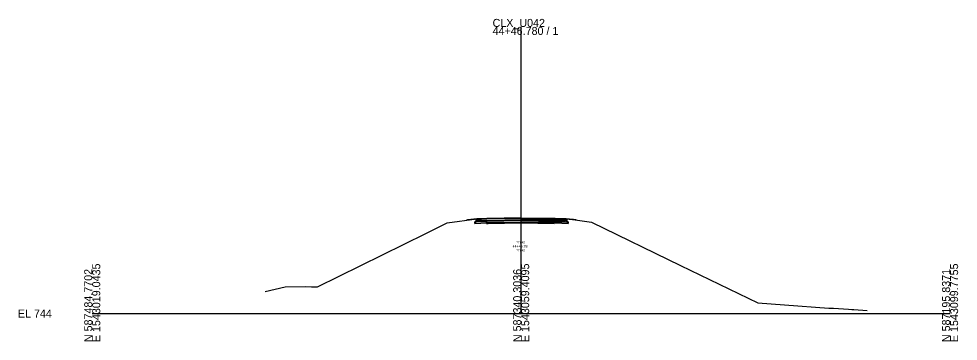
# Model space of a CAD drawing. Extents: x -26 to 1603, y -10 to 5557.
# Drawn here: x 1274.3 to 1602.8, y -9.7 to 103.1 of the extents above; entities that cross this region are included whole.
import ezdxf

# ---------------------------------------------------------------- set-up
doc = ezdxf.new("R2010")
doc.units = 0
for name, color, linetype in [('GK_Cells', 7, 'Continuous'), ('XS_P_Annotation', 7, 'Continuous'), ('XS_P_Earthwork_Shapes', 7, 'Continuous'), ('XS_P_Finished_Grade', 7, 'Continuous'), ('XS_P_Pavt_Layers', 7, 'Continuous'), ('XS_P_Pavt_Surface', 7, 'Continuous'), ('XS_P_Shoulder_Layers', 7, 'Continuous'), ('XS_P_Shoulder_Surface', 7, 'Continuous'), ('XS_P_Subgrade', 7, 'Continuous'), ('XS_X_Ground_Line', 7, 'Continuous'), ('XS_X_Pavt', 7, 'Continuous')]:
    doc.layers.add(name, color=color, linetype=linetype)

msp = doc.modelspace()

# ---------------------------------------------------------------- linework, layer by layer
at = {"layer": 'GK_Cells'}
for p, q in [((1450, 0), (1450, 100.27)), ((1300, 0), (1450, 0)), ((1450, 0), (1600, 0))]:
    msp.add_line(p, q, dxfattribs=at)
at = {"layer": 'XS_P_Earthwork_Shapes'}
for points in [[(1430.85, 32.64), (1433.47, 33), (1431.19, 32.81)], [(1430.85, 32.64), (1433.47, 33), (1431.19, 32.81)], [(1433.47, 33), (1431.19, 32.81), (1430.85, 32.64)], [(1433.47, 33), (1431.19, 32.81), (1430.85, 32.64)], [(1434.54, 33.09), (1433.47, 33), (1434.49, 33.14), (1434.54, 33.14)], [(1434.54, 33.09), (1433.47, 33), (1434.49, 33.14), (1434.54, 33.14)], [(1434.54, 33.09), (1433.47, 33), (1434.49, 33.14), (1434.54, 33.14)], [(1434.54, 33.09), (1433.47, 33), (1434.49, 33.14), (1434.54, 33.14)], [(1434.54, 33.14), (1438.46, 33.23), (1449.95, 33.42), (1461.72, 33.3), (1462.03, 33.29), (1465.5, 33.23), (1465.5, 32.48), (1462.03, 32.54), (1461.72, 32.55), (1461.49, 32.55), (1449.95, 32.67), (1438.46, 32.48), (1437.93, 32.47), (1434.54, 32.39), (1434.54, 32.82), (1434.61, 32.83), (1434.61, 33.1), (1434.54, 33.09)], [(1434.54, 33.14), (1438.46, 33.23), (1449.95, 33.42), (1461.72, 33.3), (1462.03, 33.29), (1465.5, 33.23), (1465.5, 32.48), (1462.03, 32.54), (1461.72, 32.55), (1461.49, 32.55), (1449.95, 32.67), (1438.46, 32.48), (1437.93, 32.47), (1434.54, 32.39), (1434.54, 32.82), (1434.61, 32.83), (1434.61, 33.1), (1434.54, 33.09)], [(1434.54, 33.14), (1438.46, 33.23), (1449.95, 33.42), (1461.72, 33.3), (1462.03, 33.29), (1465.5, 33.23), (1465.5, 32.48), (1462.03, 32.54), (1461.72, 32.55), (1461.49, 32.55), (1449.95, 32.67), (1438.46, 32.48), (1437.93, 32.47), (1434.54, 32.39), (1434.54, 32.82), (1434.61, 32.83), (1434.61, 33.1), (1434.54, 33.09)], [(1434.54, 33.14), (1438.46, 33.23), (1449.95, 33.42), (1461.72, 33.3), (1462.03, 33.29), (1465.5, 33.23), (1465.5, 32.48), (1462.03, 32.54), (1461.72, 32.55), (1461.49, 32.55), (1449.95, 32.67), (1438.46, 32.48), (1437.93, 32.47), (1434.54, 32.39), (1434.54, 32.82), (1434.61, 32.83), (1434.61, 33.1), (1434.54, 33.09)], [(1465.5, 33.23), (1465.78, 33.22), (1466.49, 33.12), (1468.25, 32.87), (1465.65, 33.09), (1465.65, 32.82), (1465.98, 32.8), (1465.98, 32.05), (1466.48, 32.03), (1466.48, 31.53), (1461.96, 31.71), (1461.49, 31.72), (1461.49, 32.55), (1461.72, 32.55), (1462.03, 32.54), (1465.5, 32.48)], [(1465.5, 33.23), (1465.78, 33.22), (1466.49, 33.12), (1468.25, 32.87), (1465.65, 33.09), (1465.65, 32.82), (1465.98, 32.8), (1465.98, 32.05), (1466.48, 32.03), (1466.48, 31.53), (1461.96, 31.71), (1461.49, 31.72), (1461.49, 32.55), (1461.72, 32.55), (1462.03, 32.54), (1465.5, 32.48)], [(1465.5, 33.23), (1465.78, 33.22), (1466.49, 33.12), (1468.25, 32.87), (1465.65, 33.09), (1465.65, 32.82), (1465.98, 32.8), (1465.98, 32.05), (1466.48, 32.03), (1466.48, 31.53), (1461.96, 31.71), (1461.49, 31.72), (1461.49, 32.55), (1461.72, 32.55), (1462.03, 32.54), (1465.5, 32.48)], [(1465.5, 33.23), (1465.78, 33.22), (1466.49, 33.12), (1468.25, 32.87), (1465.65, 33.09), (1465.65, 32.82), (1465.98, 32.8), (1465.98, 32.05), (1466.48, 32.03), (1466.48, 31.53), (1461.96, 31.71), (1461.49, 31.72), (1461.49, 32.55), (1461.72, 32.55), (1462.03, 32.54), (1465.5, 32.48)], [(1468.25, 32.87), (1469.06, 32.8), (1469.2, 32.73)], [(1468.25, 32.87), (1469.2, 32.73), (1469.06, 32.8)], [(1468.25, 32.87), (1469.2, 32.73), (1469.06, 32.8)], [(1468.25, 32.87), (1469.2, 32.73), (1469.06, 32.8)], [(1434.54, 32.82), (1434.54, 32.39), (1437.93, 32.47), (1437.93, 31.71), (1433.77, 31.54), (1433.77, 32.04), (1434.27, 32.06), (1434.27, 32.81)], [(1437.93, 32.47), (1437.93, 31.71), (1433.77, 31.54), (1433.77, 32.04), (1434.27, 32.06), (1434.27, 32.81), (1434.54, 32.82), (1434.54, 32.39)], [(1434.54, 32.82), (1434.54, 32.39), (1437.93, 32.47), (1437.93, 31.71), (1433.77, 31.54), (1433.77, 32.04), (1434.27, 32.06), (1434.27, 32.81)], [(1434.54, 32.82), (1434.54, 32.39), (1437.93, 32.47), (1437.93, 31.71), (1433.77, 31.54), (1433.77, 32.04), (1434.27, 32.06), (1434.27, 32.81)], [(1461.49, 32.55), (1461.49, 31.72), (1450, 31.9), (1438.04, 31.71), (1437.93, 31.71), (1437.93, 32.47), (1438.46, 32.48), (1449.95, 32.67)], [(1437.93, 32.47), (1437.93, 31.71), (1438.04, 31.71), (1450, 31.9), (1461.49, 31.72), (1461.49, 32.55), (1449.95, 32.67), (1438.46, 32.48)], [(1437.93, 31.71), (1438.04, 31.71), (1450, 31.9), (1461.49, 31.72), (1461.49, 32.55), (1449.95, 32.67), (1438.46, 32.48), (1437.93, 32.47)], [(1437.93, 31.71), (1438.04, 31.71), (1450, 31.9), (1461.49, 31.72), (1461.49, 32.55), (1449.95, 32.67), (1438.46, 32.48), (1437.93, 32.47)]]:
    msp.add_lwpolyline(points, close=True, dxfattribs=at)
at = {"layer": 'XS_P_Finished_Grade'}
for p, q in [((1434.61, 33.1), (1431.19, 32.81)), ((1465.65, 33.09), (1469.06, 32.8)), ((1431.19, 32.81), (1430.85, 32.64)), ((1469.06, 32.8), (1469.2, 32.73))]:
    msp.add_line(p, q, dxfattribs=at)
at = {"layer": 'XS_P_Pavt_Layers'}
for p, q in [((1434.61, 33.1), (1434.61, 32.83)), ((1450, 33.3), (1438, 33.11)), ((1450, 33.15), (1438, 32.96)), ((1450, 33.3), (1462, 33.11)), ((1450, 33.15), (1462, 32.96)), ((1465.65, 33.09), (1465.65, 32.82)), ((1433.77, 32.04), (1433.77, 31.54)), ((1434.27, 32.81), (1434.27, 32.06)), ((1450.02, 32.4), (1438.02, 32.21)), ((1450.02, 31.9), (1438.02, 31.71)), ((1449.98, 32.4), (1461.98, 32.21)), ((1449.98, 31.9), (1461.98, 31.71)), ((1465.98, 32.8), (1465.98, 32.05)), ((1466.48, 32.03), (1466.48, 31.53))]:
    msp.add_line(p, q, dxfattribs=at)
at = {"layer": 'XS_P_Pavt_Surface'}
for q in [(1438, 33.23), (1462, 33.23)]:
    msp.add_line((1450, 33.43), q, dxfattribs=at)
at = {"layer": 'XS_P_Shoulder_Layers'}
for p, q in [((1438.01, 32.96), (1434.27, 32.81)), ((1438, 33.11), (1434.61, 32.97)), ((1461.99, 32.96), (1465.98, 32.8)), ((1462, 33.11), (1465.64, 32.96)), ((1438.04, 32.21), (1433.77, 32.04)), ((1438.06, 31.71), (1433.77, 31.54)), ((1461.94, 31.71), (1466.48, 31.53)), ((1461.96, 32.21), (1466.48, 32.03))]:
    msp.add_line(p, q, dxfattribs=at)
at = {"layer": 'XS_P_Shoulder_Surface'}
for p, q in [((1438, 33.23), (1434.61, 33.1)), ((1462, 33.23), (1465.65, 33.09))]:
    msp.add_line(p, q, dxfattribs=at)
at = {"layer": 'XS_P_Subgrade'}
msp.add_lwpolyline([(1434.61, 33.1), (1434.61, 32.83), (1434.27, 32.81), (1434.27, 32.06), (1433.77, 32.04), (1433.77, 31.54), (1438.04, 31.71), (1450, 31.9), (1461.96, 31.71), (1466.48, 31.53), (1466.48, 32.03), (1465.98, 32.05), (1465.98, 32.8), (1465.65, 32.82), (1465.65, 33.09)], dxfattribs=at)
at = {"layer": 'XS_X_Ground_Line'}
msp.add_lwpolyline([(1360.43, 7.71), (1367.43, 9.33), (1374.65, 9.45), (1376.65, 9.37), (1378.73, 9.29), (1416.65, 28.02), (1424.14, 31.72), (1434.49, 33.14), (1438.46, 33.23), (1449.95, 33.42), (1461.72, 33.3), (1462.03, 33.29), (1465.78, 33.22), (1466.49, 33.12), (1474.61, 31.96), (1505.67, 16.79), (1532.78, 3.68), (1542.14, 3.01), (1557.59, 1.92), (1559.22, 1.82), (1562.69, 1.62), (1564.49, 1.52), (1565.58, 1.45), (1566.32, 1.41), (1570.95, 1.1)], dxfattribs=at)
at = {"layer": 'XS_X_Pavt'}
for p, q in [((1434.54, 33.14), (1434.54, 32.39)), ((1465.5, 33.23), (1465.5, 32.48)), ((1434.54, 32.39), (1437.93, 32.47)), ((1437.93, 32.47), (1438.46, 32.48)), ((1437.93, 32.47), (1437.93, 31.47)), ((1437.93, 31.47), (1438.46, 31.48)), ((1438.46, 32.48), (1449.95, 32.67)), ((1438.46, 31.48), (1449.95, 31.67)), ((1449.95, 32.67), (1461.49, 32.55)), ((1449.95, 31.67), (1461.49, 31.55)), ((1461.49, 32.55), (1461.72, 32.55)), ((1461.49, 32.55), (1461.49, 31.55)), ((1461.72, 32.55), (1462.03, 32.54)), ((1462.03, 32.54), (1465.5, 32.48))]:
    msp.add_line(p, q, dxfattribs=at)

# ---------------------------------------------------------------- texts
at = {"layer": 'GK_Cells'}
for s, p in [('CLX_U042', (1440, 100.27)), ('44+46.780 / 1', (1440, 97.47)), ('EL 744', (1274, -1.4))]:
    msp.add_text(s, height=2.8, dxfattribs=at).set_placement(p)
for s, p in [('E 1543019.0435', (1302.8, -10)), ('E 1543059.4095', (1452.8, -10)), ('E 1543099.7755', (1602.8, -10)), ('N 587484.7702', (1300, -10)), ('N 587340.3036', (1450, -10)), ('N 587195.8371', (1600, -10))]:
    msp.add_text(s, height=2.8, rotation=90, dxfattribs=at).set_placement(p)
at = {"layer": 'XS_P_Annotation'}
for s, height, p in [('44+46.78', 0.9, (1447, 23.05)), ('777.42', 0.7, (1448.31, 24.55)), ('777.42', 0.7, (1448.31, 21.75))]:
    msp.add_text(s, height=height, dxfattribs=at).set_placement(p)

doc.saveas('drawing.dxf')
